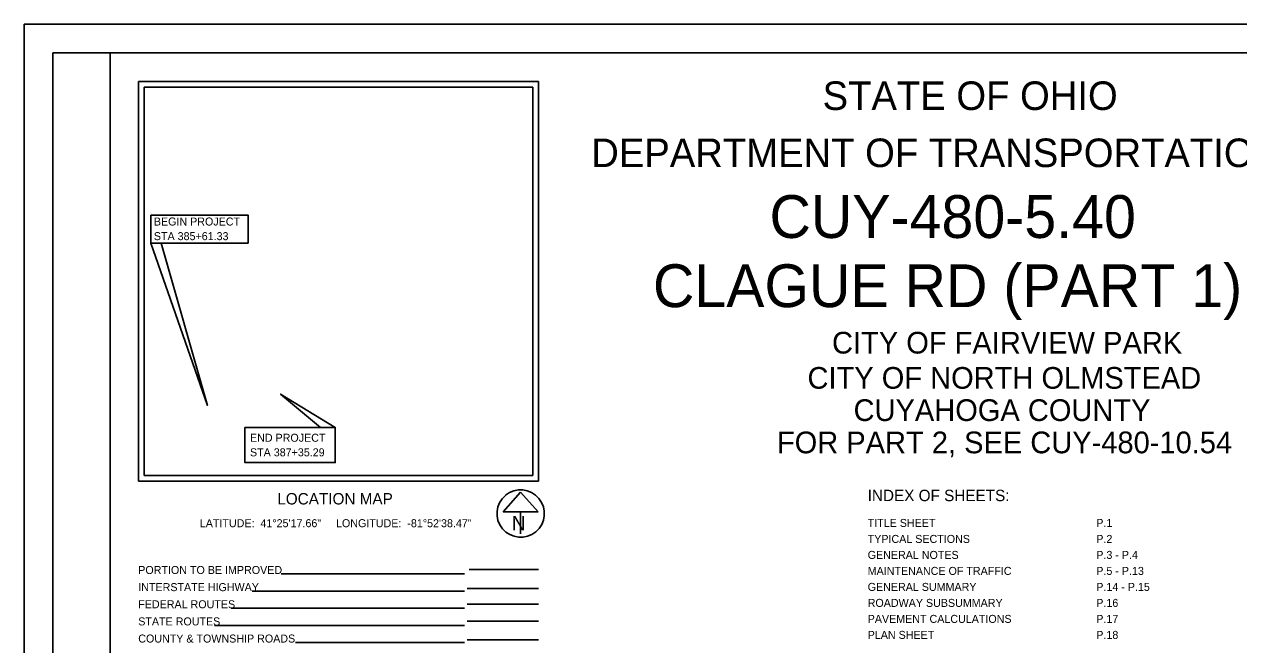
# Model space of a CAD drawing. Extents: x 0 to 34, y 0 to 22.
# Drawn here: x 0 to 21.25, y 11.14 to 22 of the extents above; entities that cross this region are included whole.
import ezdxf

# ---------------------------------------------------------------- set-up
doc = ezdxf.new("R2010")
doc.units = 0
for name, color, linetype in [('Default', 7, 'Continuous'), ('SH_Border', 7, 'Continuous'), ('SH_Cut_Line', 7, 'Continuous'), ('SH_Data', 7, 'Continuous'), ('SH_Text', 7, 'Continuous')]:
    doc.layers.add(name, color=color, linetype=linetype)

msp = doc.modelspace()

# ---------------------------------------------------------------- linework, layer by layer
at = {"layer": 'SH_Border'}
for points in [[(0.5, 21.5), (1.5, 21.5), (1.5, 0.5), (0.5, 0.5)], [(1.5, 21.5), (33.5, 21.5), (33.5, 0.5), (1.5, 0.5)]]:
    msp.add_lwpolyline(points, close=True, dxfattribs=at)
at = {"layer": 'SH_Cut_Line'}
msp.add_lwpolyline([(0, 0), (34, 0), (34, 22), (0, 22)], close=True, dxfattribs=at)
at = {"layer": 'SH_Data'}
for p, q in [((2, 21), (9, 21)), ((2, 21), (2, 14)), ((2.1, 20.9), (2.1, 14.1)), ((2.1, 20.9), (8.9, 20.9)), ((8.9, 20.9), (8.9, 14.1)), ((9, 21), (9, 14)), ((2.1, 14.1), (8.9, 14.1)), ((2.1, 14.1), (2.1, 14.1)), ((2, 14), (9, 14)), ((8.685, 13.809), (8.377, 13.468)), ((8.992, 13.468), (8.685, 13.809)), ((8.377, 13.468), (8.992, 13.468)), ((8.685, 13.468), (8.685, 13.081)), ((8.685, 13.435), (8.685, 13.435)), ((8.685, 13.435), (8.685, 13.435)), ((7.7, 12.377), (4.494, 12.377)), ((7.783, 12.455), (9, 12.455)), ((9, 12.121), (7.75, 12.121)), ((7.7, 12.077), (3.99, 12.077)), ((7.7, 11.777), (3.619, 11.777)), ((9, 11.849), (7.75, 11.849)), ((7.7, 11.477), (3.329, 11.477)), ((9, 11.549), (7.75, 11.549)), ((7.7, 11.177), (4.745, 11.177)), ((9, 11.222), (7.75, 11.222))]:
    msp.add_line(p, q, dxfattribs=at)
msp.add_arc((8.685, 13.435), 0.415, 129.7798, 129.7633, dxfattribs=at)
at = {"layer": 'SH_Text'}
for points in [[(2.216, 18.661), (3.916, 18.661), (3.916, 18.17), (2.216, 18.17)], [(2.393, 18.17), (3.204, 15.327), (2.216, 18.17)], [(5.44, 14.944), (4.484, 15.525), (5.185, 14.944)], [(3.86, 14.944), (5.44, 14.944), (5.44, 14.326), (3.86, 14.326)]]:
    msp.add_lwpolyline(points, close=True, dxfattribs=at)

# ---------------------------------------------------------------- texts
at = {"layer": 'Default'}
for s, height, p in [('CITY OF FAIRVIEW PARK', 0.38, (14.133, 16.236)), ('CITY OF NORTH OLMSTEAD', 0.38, (13.704, 15.62)), ('CUYAHOGA COUNTY', 0.38, (14.51, 15.055)), ('FOR PART 2, SEE CUY-480-10.54', 0.38, (13.169, 14.49)), ('TITLE SHEET', 0.14, (14.757, 13.201)), ('P.1', 0.14, (18.757, 13.201)), ('TYPICAL SECTIONS', 0.14, (14.757, 12.921)), ('P.2', 0.14, (18.757, 12.921)), ('GENERAL NOTES', 0.14, (14.757, 12.641)), ('P.3', 0.14, (18.757, 12.641)), (' - P.4', 0.14, (19.038, 12.641)), ('MAINTENANCE OF TRAFFIC', 0.14, (14.757, 12.361)), ('P.5 - P.13', 0.14, (18.757, 12.361)), ('GENERAL SUMMARY', 0.14, (14.757, 12.081)), ('P.14 - P.15', 0.14, (18.757, 12.081)), ('ROADWAY SUBSUMMARY', 0.14, (14.757, 11.801)), ('P.16', 0.14, (18.757, 11.801)), ('PAVEMENT CALCULATIONS', 0.14, (14.757, 11.521)), ('P.17', 0.14, (18.757, 11.521)), ('PLAN SHEET', 0.14, (14.757, 11.241)), ('P.18', 0.14, (18.757, 11.241))]:
    msp.add_text(s, height=height, dxfattribs=at).set_placement(p)
at = {"layer": 'SH_Data'}
msp.add_text('N', height=0.25, dxfattribs=at).set_placement((8.529, 13.144))
at = {"layer": 'SH_Text'}
for s, height, p in [('STATE OF OHIO', 0.5, (13.968, 20.5)), ('DEPARTMENT OF TRANSPORTATION', 0.5, (9.92, 19.5)), ('CUY-480-5.40', 0.75, (13.039, 18.259)), ('BEGIN PROJECT', 0.14, (2.267, 18.477)), ('STA 385+61.33', 0.14, (2.267, 18.221)), ('CLAGUE RD (PART 1)', 0.75, (11, 17.048)), ('END PROJECT', 0.14, (3.949, 14.692)), ('STA 387+35.29', 0.14, (3.949, 14.437)), ('INDEX OF SHEETS:', 0.2, (14.757, 13.652)), ('LOCATION MAP', 0.2, (4.427, 13.594)), ('LATITUDE:  41°25\'17.66"     LONGITUDE:  -81°52\'38.47"', 0.14, (3.071, 13.196)), ('PORTION TO BE IMPROVED', 0.14, (1.994, 12.377)), ('INTERSTATE HIGHWAY', 0.14, (1.994, 12.077)), ('FEDERAL ROUTES', 0.14, (1.994, 11.777)), ('STATE ROUTES', 0.14, (1.994, 11.477)), ('COUNTY & TOWNSHIP ROADS', 0.14, (1.994, 11.177))]:
    msp.add_text(s, height=height, dxfattribs=at).set_placement(p)

doc.saveas('drawing.dxf')
